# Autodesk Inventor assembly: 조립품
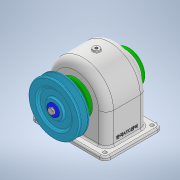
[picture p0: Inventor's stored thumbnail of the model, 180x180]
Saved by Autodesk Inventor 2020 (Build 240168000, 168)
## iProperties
Created: 2022-09
Part Number: 조립품
Document SubType Name: Assembly
Designer: Administrator
Author: Administrator
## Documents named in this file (16)
- C:\Users\Administrator\Desktop\720906V1022\조립품.iam
- C:\Users\Administrator\Desktop\720906V1022\1. 본체.ipt
- C:\Users\Administrator\Desktop\720906V1022\V-벨트풀리.ipt
- C:\Users\Administrator\Desktop\720906V1022\뒤커버.ipt
- C:\Users\Administrator\Desktop\720906V1022\베어링 6203.ipt
- C:\Users\Administrator\Desktop\720906V1022\스퍼기어.ipt
- C:\Users\Administrator\Desktop\720906V1022\앞커버.ipt
- C:\Users\Administrator\Desktop\720906V1022\오일 실 17 x 30 x 8.ipt
- C:\Users\Administrator\Desktop\720906V1022\축.ipt
- C:\Users\Administrator\Desktop\720906V1022\칼라.ipt
- C:\Users\Administrator\Desktop\720906V1022\키 6 x 6 x 22.ipt
- C:\Users\Administrator\Desktop\720906V1022\키 5 x 5 x 18.ipt
- C:\Users\Administrator\Desktop\720906V1022\멈춤나사 M4 x 10.ipt
- C:\Users\Administrator\Desktop\720906V1022\와셔 6 x 22.ipt
- C:\Users\Administrator\Desktop\720906V1022\육각머리볼트 M3 x 8.ipt
- C:\Users\Administrator\Desktop\720906V1022\볼트 M3 x 10.ipt
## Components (11 placed, 3 different names)
1. 1. 본체:1
2. 1. 본체:2
3. V-벨트풀리:1 — 플러쉬:1, 플러쉬:2
4. ISO 4762 M3 x 10:1
5. ISO 4762 M3 x 10:2
6. ISO 4762 M3 x 10:3
7. ISO 4762 M3 x 10:4
8. ISO 4762 M3 x 10:5
9. ISO 4762 M3 x 10:6
10. ISO 4762 M3 x 10:7
11. ISO 4762 M3 x 10:8
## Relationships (2: Flush 2)
- 플러쉬:1 [Flush]: V-벨트풀리:1
- 플러쉬:2 [Flush]: V-벨트풀리:1
